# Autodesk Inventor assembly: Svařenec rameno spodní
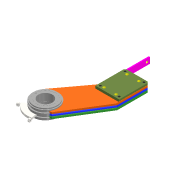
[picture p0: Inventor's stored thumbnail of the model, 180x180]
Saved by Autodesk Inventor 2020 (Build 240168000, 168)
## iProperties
Created: 2025-03
Part Number: Svařenec rameno spodní
Document SubType Name: Assembly
Designer: doma
Mass: 12553.6 g
Surface Area: 3574.23 cm^2
Volume: 1599.19 cm^3
Density: 7.85 g/cm^3
Author: doma
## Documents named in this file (13)
- C:\Users\doma\Desktop\Pásovka záloha\Workgroups\NotInProject\Svařenec rameno spodní.iam
- C:\Users\doma\Desktop\Pásovka záloha\Workgroups\NotInProject\Rameno spodní 1.ipt
- C:\Users\doma\Desktop\Pásovka záloha\Workgroups\NotInProject\Středový díl spodního ramene.ipt
- C:\Users\doma\Desktop\Pásovka záloha\Workgroups\NotInProject\Deska spodního ramene.ipt
- C:\Users\doma\Desktop\Pásovka záloha\Workgroups\NotInProject\Rameno spodní 2.ipt
- C:\Users\doma\Desktop\Pásovka záloha\Workgroups\NotInProject\Výztuha spodního ramene 245.ipt
- C:\Users\doma\Desktop\Pásovka záloha\Workgroups\NotInProject\Výztuha spodního ramene 160.ipt
- C:\Users\doma\Desktop\Pásovka záloha\Workgroups\NotInProject\Výztuha spodního ramene 100.ipt
- C:\Users\doma\Desktop\Pásovka záloha\Workgroups\NotInProject\Výztuha spodního ramene 113.ipt
- C:\Users\doma\Desktop\Pásovka záloha\Workgroups\NotInProject\Výztuha spodního ramene 228.ipt
- C:\Users\doma\Desktop\Pásovka záloha\Workgroups\NotInProject\držák pružiny.ipt
- C:\Users\doma\Desktop\Pásovka záloha\Workgroups\NotInProject\Doraz otočný 2.ipt
- C:\Users\doma\Desktop\Pásovka záloha\Workgroups\NotInProject\Matice dorazu.ipt
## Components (13 placed, 12 different names)
1. Rameno spodní 1 — Proti sobě:3, Proti sobě:4, Úhel:6, Proti sobě:6, Stejný směr:2, Stejný směr:3, Stejný směr:4, Proti sobě:12, Proti sobě:14, Proti sobě:16, Proti sobě:18
2. Středový díl spodního ramene:1 — Proti sobě:3, Proti sobě:4, Úhel:6, Proti sobě:7, Proti sobě:8, Proti sobě:20, Proti sobě:21, Proti sobě:22
3. Deska spodního ramene:1 — Proti sobě:6, Stejný směr:2, Stejný směr:3, Úhel:7
4. Rameno spodní 2:1 — Proti sobě:7, Stejný směr:4, Proti sobě:8, Proti sobě:9, Stejný směr:5, Stejný směr:6, Proti sobě:11, Stejný směr:7, Stejný směr:8, Stejný směr:9, Stejný směr:10, Stejný směr:11, Proti sobě:15, Stejný směr:12, Proti sobě:19, Úhel:1
5. Výztuha spodního ramene 245:1 — Proti sobě:9, Stejný směr:5, Proti sobě:17
6. Výztuha spodního ramene 160:1 — Stejný směr:6, Proti sobě:11, Stejný směr:7, Proti sobě:13, Proti sobě:17
7. Výztuha spodního ramene 100:1 — Proti sobě:12, Stejný směr:8, Proti sobě:13
8. Výztuha spodního ramene 113:1 — Proti sobě:14, Stejný směr:9, Stejný směr:10
9. Výztuha spodního ramene 228:1 — Stejný směr:11, Proti sobě:15, Proti sobě:16
10. držák pružiny:1 — Proti sobě:18, Stejný směr:12, Proti sobě:19
11. Doraz otočný 2:1 — Proti sobě:20, Proti sobě:21, Úhel:1, Stejný směr:13, Stejný směr:14, Tečnost:1, Stejný směr:15, Stejný směr:16, Tečnost:2
12. Matice dorazu:1 — Stejný směr:15, Stejný směr:16, Tečnost:2
13. Matice dorazu:2 — Stejný směr:13, Stejný směr:14, Tečnost:1
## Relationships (38: Mate 18, Flush 15, Angle 3, Tangent 2)
- Proti sobě:3 [Mate]: Rameno spodní 1 ↔ Středový díl spodního ramene:1
- Proti sobě:4 [Mate]: Rameno spodní 1 ↔ Středový díl spodního ramene:1
- Úhel:6 [Angle]: Rameno spodní 1 ↔ Středový díl spodního ramene:1
- Proti sobě:6 [Mate]: Rameno spodní 1 ↔ Deska spodního ramene:1
- Stejný směr:2 [Flush]: Rameno spodní 1 ↔ Deska spodního ramene:1
- Stejný směr:3 [Flush]: Rameno spodní 1 ↔ Deska spodního ramene:1
- Proti sobě:7 [Mate]: Středový díl spodního ramene:1 ↔ Rameno spodní 2:1
- Stejný směr:4 [Flush]: Rameno spodní 1 ↔ Rameno spodní 2:1
- Proti sobě:8 [Mate]: Středový díl spodního ramene:1 ↔ Rameno spodní 2:1
- Proti sobě:9 [Mate]: Rameno spodní 2:1 ↔ Výztuha spodního ramene 245:1
- Stejný směr:5 [Flush]: Rameno spodní 2:1 ↔ Výztuha spodního ramene 245:1
- Stejný směr:6 [Flush]: Rameno spodní 2:1 ↔ Výztuha spodního ramene 160:1
- Proti sobě:11 [Mate]: Rameno spodní 2:1 ↔ Výztuha spodního ramene 160:1
- Stejný směr:7 [Flush]: Rameno spodní 2:1 ↔ Výztuha spodního ramene 160:1
- Proti sobě:12 [Mate]: Rameno spodní 1 ↔ Výztuha spodního ramene 100:1
- Stejný směr:8 [Flush]: Rameno spodní 2:1 ↔ Výztuha spodního ramene 100:1
- Proti sobě:13 [Mate]: Výztuha spodního ramene 160:1 ↔ Výztuha spodního ramene 100:1
- Proti sobě:14 [Mate]: Rameno spodní 1 ↔ Výztuha spodního ramene 113:1
- Stejný směr:9 [Flush]: Rameno spodní 2:1 ↔ Výztuha spodního ramene 113:1
- Stejný směr:10 [Flush]: Rameno spodní 2:1 ↔ Výztuha spodního ramene 113:1
- Stejný směr:11 [Flush]: Rameno spodní 2:1 ↔ Výztuha spodního ramene 228:1
- Proti sobě:15 [Mate]: Rameno spodní 2:1 ↔ Výztuha spodního ramene 228:1
- Proti sobě:16 [Mate]: Rameno spodní 1 ↔ Výztuha spodního ramene 228:1
- Proti sobě:17 [Mate]: Výztuha spodního ramene 245:1 ↔ Výztuha spodního ramene 160:1
- Proti sobě:18 [Mate]: Rameno spodní 1 ↔ držák pružiny:1
- Stejný směr:12 [Flush]: Rameno spodní 2:1 ↔ držák pružiny:1
- Proti sobě:19 [Mate]: Rameno spodní 2:1 ↔ držák pružiny:1
- Proti sobě:20 [Mate]: Středový díl spodního ramene:1 ↔ Doraz otočný 2:1
- Proti sobě:21 [Mate]: Středový díl spodního ramene:1 ↔ Doraz otočný 2:1
- Úhel:1 [Angle]: Rameno spodní 2:1 ↔ Doraz otočný 2:1
- Stejný směr:13 [Flush]: Doraz otočný 2:1 ↔ Matice dorazu:2
- Stejný směr:14 [Flush]: Doraz otočný 2:1 ↔ Matice dorazu:2
- Tečnost:1 [Tangent]: Doraz otočný 2:1 ↔ Matice dorazu:2
- Stejný směr:15 [Flush]: Doraz otočný 2:1 ↔ Matice dorazu:1
- Stejný směr:16 [Flush]: Doraz otočný 2:1 ↔ Matice dorazu:1
- Tečnost:2 [Tangent]: Doraz otočný 2:1 ↔ Matice dorazu:1
- Proti sobě:22 [Mate]: Středový díl spodního ramene:1
- Úhel:7 [Angle]: Deska spodního ramene:1
